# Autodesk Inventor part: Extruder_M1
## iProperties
Shininess: 64.0
Length Units: 11269
Angle Units: 11279
Time Units: 11290
Mass Units: 11283
Length Display Precision: 3
Angle Display Precision: 2
Compacted: True
Part Number: Extruder_M1
Document SubType Name: Modeling
Created: 2003-07
Material: Standard
Designer: Heinemann
Manufacturer: Standard
Standards Organization: Custom
Density: 0.0
Volumn: 0.0
Area: 0.0
PropertySet Name: Model Information
Control State: 0
Master: False
Checked Out: False
Author: Heinemann
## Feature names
1. Extrusion1
2. Extrusion2
3. Extrusion3
4. Extrusion6
5. Bohrung1 [Hole]
6. Extrusion7
